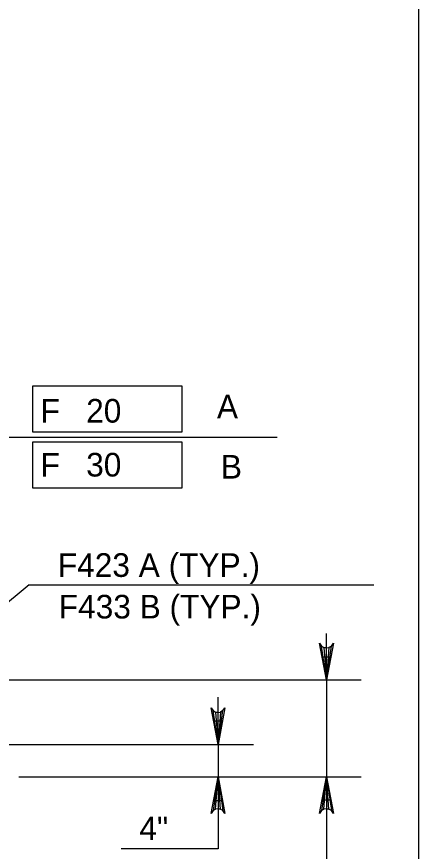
# Model space of a CAD drawing. Extents: x 638340 to 640242, y 295465 to 298435.
# Drawn here: x 640051.5 to 640102.5, y 298208.5 to 298314.4 of the extents above; entities that cross this region are included whole.
import ezdxf

# ---------------------------------------------------------------- set-up
doc = ezdxf.new("R2010")
doc.units = 0
for name, color, linetype in [('2', 7, 'Continuous'), ('Level 3', 7, 'Continuous'), ('Level 4', 7, 'Continuous')]:
    doc.layers.add(name, color=color, linetype=linetype)

msp = doc.modelspace()

# ---------------------------------------------------------------- linework, layer by layer
at = {"layer": '2'}
msp.add_line((640102.46, 298420.46), (640102.46, 297856.46), dxfattribs=at)
at = {"layer": 'Level 3'}
for p, q in [((640090.81, 298233.23), (640090.81, 298236.18)), ((640039.27, 298230.28), (640095.23, 298230.28)), ((640090.81, 298230.28), (640090.81, 298218.01)), ((640077.06, 298225.09), (640077.06, 298228.09)), ((640048.61, 298222.1), (640081.55, 298222.1)), ((640077.06, 298222.1), (640077.06, 298218.01)), ((640051.79, 298218.01), (640095.23, 298218.01)), ((640051.82, 298218.01), (640081.55, 298218.01)), ((640077.06, 298215.01), (640077.06, 298208.85)), ((640090.81, 298215.06), (640090.81, 298198.16)), ((640077.06, 298208.85), (640064.79, 298208.85))]:
    msp.add_line(p, q, dxfattribs=at)
for points in [[(640090.81, 298230.28), (640089.93, 298234.94), (640090.18, 298234.58), (640090.49, 298234.39), (640090.81, 298234.34), (640091.12, 298234.39), (640091.43, 298234.58), (640091.68, 298234.94), (640090.81, 298230.28), (640091.43, 298234.58), (640091.12, 298234.39), (640090.81, 298230.28), (640090.81, 298234.34), (640090.49, 298234.39), (640090.81, 298230.28), (640090.18, 298234.58)], [(640077.06, 298222.1), (640076.19, 298226.75), (640076.43, 298226.39), (640076.75, 298226.21), (640077.06, 298226.15), (640077.37, 298226.21), (640077.68, 298226.39), (640077.93, 298226.75), (640077.06, 298222.1), (640077.68, 298226.39), (640077.37, 298226.21), (640077.06, 298222.1), (640077.06, 298226.15), (640076.75, 298226.21), (640077.06, 298222.1), (640076.43, 298226.39)], [(640077.06, 298218.01), (640077.93, 298213.36), (640077.68, 298213.72), (640077.37, 298213.9), (640077.06, 298213.95), (640076.75, 298213.9), (640076.43, 298213.72), (640076.19, 298213.36), (640077.06, 298218.01), (640076.43, 298213.72), (640076.75, 298213.9), (640077.06, 298218.01), (640077.06, 298213.95), (640077.37, 298213.9), (640077.06, 298218.01), (640077.68, 298213.72)], [(640090.81, 298218.01), (640091.68, 298213.36), (640091.43, 298213.72), (640091.12, 298213.9), (640090.81, 298213.95), (640090.49, 298213.9), (640090.18, 298213.72), (640089.93, 298213.36), (640090.81, 298218.01), (640090.18, 298213.72), (640090.49, 298213.9), (640090.81, 298218.01), (640090.81, 298213.95), (640091.12, 298213.9), (640090.81, 298218.01), (640091.43, 298213.72)]]:
    msp.add_lwpolyline(points, dxfattribs=at)
for points in [[(640090.31, 298233.23), (640091.3, 298233.23), (640090.81, 298230.28)], [(640076.56, 298225.09), (640077.56, 298225.09), (640077.06, 298222.1)], [(640076.56, 298215.01), (640077.56, 298215.01), (640077.06, 298218.01)], [(640090.31, 298215.06), (640091.3, 298215.06), (640090.81, 298218.01)]]:
    msp.add_lwpolyline(points, close=True, dxfattribs=at)
at = {"layer": 'Level 4'}
for p, q in [((640053.57, 298267.6), (640072.47, 298267.6)), ((640053.57, 298261.7), (640053.57, 298267.6)), ((640072.47, 298267.6), (640072.47, 298261.7)), ((640072.47, 298261.7), (640053.57, 298261.7)), ((640048.76, 298261.08), (640084.56, 298261.08)), ((640053.57, 298260.5), (640072.47, 298260.5)), ((640053.57, 298254.6), (640053.57, 298260.5)), ((640072.47, 298260.5), (640072.47, 298254.6)), ((640072.47, 298254.6), (640053.57, 298254.6)), ((640053.12, 298242.35), (640047.05, 298237.34)), ((640053.12, 298242.35), (640096.8, 298242.35))]:
    msp.add_line(p, q, dxfattribs=at)

# ---------------------------------------------------------------- texts
at = {"layer": 'Level 3'}
msp.add_text('4"', height=3, dxfattribs=at).set_placement((640067.08, 298209.96))
at = {"layer": 'Level 4'}
for s, height, p in [('F   20', 3, (640054.54, 298262.93)), ('A', 3, (640076.92, 298263.46)), ('F   30', 3, (640054.54, 298256.09)), ('B', 3, (640077.42, 298255.83)), ('F423 A (TYP.)', 3.0001, (640056.74, 298243.36)), ('F433 B (TYP.)', 3.0001, (640056.86, 298238.08))]:
    msp.add_text(s, height=height, dxfattribs=at).set_placement(p)

doc.saveas('drawing.dxf')
